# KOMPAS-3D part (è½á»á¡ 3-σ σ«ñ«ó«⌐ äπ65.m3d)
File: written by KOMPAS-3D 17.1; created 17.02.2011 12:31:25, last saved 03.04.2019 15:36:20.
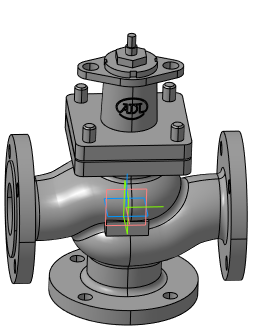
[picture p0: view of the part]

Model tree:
1. Плоскость XY
2. Плоскость ZX
3. Плоскость ZY
4. Ось X
5. Ось Y
6. Ось Z
7. Начало координат
8. Операция без истории:3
